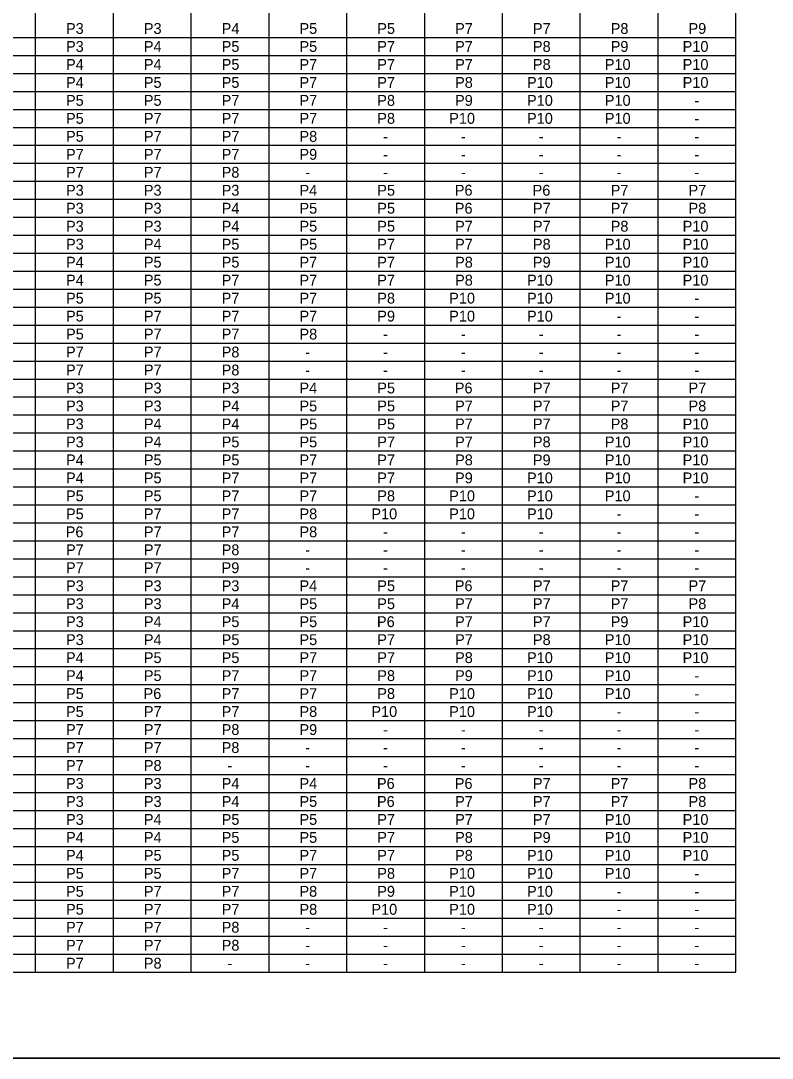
# Model space of a CAD drawing. Extents: x 637580 to 641008, y 294594 to 295782.
# Drawn here: x 640328.9 to 640536.7, y 295202.6 to 295489.6 of the extents above; entities that cross this region are included whole.
import ezdxf

# ---------------------------------------------------------------- set-up
doc = ezdxf.new("R2010")
doc.units = 0
doc.layers.add('1', color=7, linetype='Continuous')
doc.layers.add('2', color=7, linetype='Continuous')

msp = doc.modelspace()

# ---------------------------------------------------------------- linework, layer by layer
at = {"layer": '1'}
for p, q in [((640526.66, 295226.43), (640526.66, 295743.08)), ((640191.43, 295445.22), (640526.66, 295445.22)), ((640191.43, 295390.52), (640526.66, 295390.52)), ((640191.43, 295335.82), (640526.66, 295335.82)), ((640191.43, 295281.12), (640526.66, 295281.12)), ((640191.43, 295226.43), (640526.66, 295226.43)), ((640929.31, 295202.63), (640143.31, 295202.63)), ((640143.31, 295202.63), (640729.31, 295202.63))]:
    msp.add_line(p, q, dxfattribs=at)
at = {"layer": '2'}
for p, q in [((640333.02, 295226.43), (640333.02, 295728.06)), ((640354.53, 295226.43), (640354.53, 295728.06)), ((640376.05, 295226.43), (640376.05, 295728.06)), ((640397.56, 295226.43), (640397.56, 295728.06)), ((640419.08, 295226.43), (640419.08, 295728.06)), ((640440.6, 295226.43), (640440.6, 295728.06)), ((640462.11, 295226.43), (640462.11, 295728.06)), ((640483.63, 295226.43), (640483.63, 295728.06)), ((640505.14, 295226.43), (640505.14, 295728.06)), ((640218.95, 295485), (640526.66, 295485)), ((640218.95, 295480.02), (640526.66, 295480.02)), ((640218.95, 295475.05), (640526.66, 295475.05)), ((640218.95, 295470.08), (640526.66, 295470.08)), ((640218.95, 295465.11), (640526.66, 295465.11)), ((640218.95, 295460.13), (640526.66, 295460.13)), ((640218.95, 295455.16), (640526.66, 295455.16)), ((640218.95, 295450.19), (640526.66, 295450.19)), ((640218.95, 295440.24), (640526.66, 295440.24)), ((640218.95, 295435.27), (640526.66, 295435.27)), ((640218.95, 295430.3), (640526.66, 295430.3)), ((640218.95, 295425.33), (640526.66, 295425.33)), ((640218.95, 295420.35), (640526.66, 295420.35)), ((640218.95, 295415.38), (640526.66, 295415.38)), ((640218.95, 295410.41), (640526.66, 295410.41)), ((640218.95, 295405.44), (640526.66, 295405.44)), ((640218.95, 295400.46), (640526.66, 295400.46)), ((640218.95, 295395.49), (640526.66, 295395.49)), ((640218.95, 295385.55), (640526.66, 295385.55)), ((640218.95, 295380.57), (640526.66, 295380.57)), ((640218.95, 295375.6), (640526.66, 295375.6)), ((640218.95, 295370.63), (640526.66, 295370.63)), ((640218.95, 295365.66), (640526.66, 295365.66)), ((640218.95, 295360.68), (640526.66, 295360.68)), ((640218.95, 295355.71), (640526.66, 295355.71)), ((640218.95, 295350.74), (640526.66, 295350.74)), ((640218.95, 295345.77), (640526.66, 295345.77)), ((640218.95, 295340.79), (640526.66, 295340.79)), ((640218.95, 295330.85), (640526.66, 295330.85)), ((640218.95, 295325.88), (640526.66, 295325.88)), ((640218.95, 295320.9), (640526.66, 295320.9)), ((640218.95, 295315.93), (640526.66, 295315.93)), ((640218.95, 295310.96), (640526.66, 295310.96)), ((640218.95, 295305.99), (640526.66, 295305.99)), ((640218.95, 295301.01), (640526.66, 295301.01)), ((640218.95, 295296.04), (640526.66, 295296.04)), ((640218.95, 295291.07), (640526.66, 295291.07)), ((640218.95, 295286.1), (640526.66, 295286.1)), ((640218.95, 295276.15), (640526.66, 295276.15)), ((640218.95, 295271.18), (640526.66, 295271.18)), ((640218.95, 295266.21), (640526.66, 295266.21)), ((640218.95, 295261.23), (640526.66, 295261.23)), ((640218.95, 295256.26), (640526.66, 295256.26)), ((640218.95, 295251.29), (640526.66, 295251.29)), ((640218.95, 295246.32), (640526.66, 295246.32)), ((640218.95, 295241.34), (640526.66, 295241.34)), ((640218.95, 295236.37), (640526.66, 295236.37)), ((640218.95, 295231.4), (640526.66, 295231.4))]:
    msp.add_line(p, q, dxfattribs=at)

# ---------------------------------------------------------------- texts
at = {"layer": '1'}
for s, p in [('P3', (640341.42, 295485.98)), ('P3', (640362.94, 295485.98)), ('P4', (640384.46, 295485.98)), ('P5', (640405.97, 295485.98)), ('P5', (640427.49, 295485.98)), ('P7', (640449, 295485.98)), ('P7', (640470.52, 295485.98)), ('P8', (640492.03, 295485.98)), ('P9', (640513.54, 295485.98)), ('P3', (640341.42, 295481.01)), ('P4', (640362.94, 295481.01)), ('P5', (640384.46, 295481.01)), ('P5', (640405.97, 295481)), ('P7', (640427.49, 295481.01)), ('P7', (640449, 295481.01)), ('P8', (640470.52, 295481.01)), ('P9', (640492.02, 295481.01)), ('P10', (640511.92, 295481.01)), ('P4', (640341.42, 295476.04)), ('P4', (640362.94, 295476.04)), ('P5', (640384.46, 295476.04)), ('P7', (640405.97, 295476.03)), ('P7', (640427.49, 295476.04)), ('P7', (640449, 295476.04)), ('P8', (640470.52, 295476.04)), ('P10', (640490.4, 295476.04)), ('P10', (640511.92, 295476.04)), ('P4', (640341.42, 295471.06)), ('P5', (640362.94, 295471.06)), ('P5', (640384.46, 295471.06)), ('P7', (640405.97, 295471.06)), ('P7', (640427.49, 295471.06)), ('P8', (640449, 295471.06)), ('P10', (640468.89, 295471.06)), ('P10', (640490.4, 295471.06)), ('P10', (640511.92, 295471.06)), ('P5', (640341.42, 295466.09)), ('P5', (640362.94, 295466.09)), ('P7', (640384.46, 295466.09)), ('P7', (640405.97, 295466.09)), ('P8', (640427.49, 295466.09)), ('P9', (640448.99, 295466.09)), ('P10', (640468.89, 295466.09)), ('P10', (640490.4, 295466.09)), ('-', (640515.17, 295466.09)), ('P5', (640341.42, 295461.12)), ('P7', (640362.94, 295461.12)), ('P7', (640384.46, 295461.12)), ('P7', (640405.97, 295461.11)), ('P8', (640427.49, 295461.12)), ('P10', (640447.37, 295461.12)), ('P10', (640468.89, 295461.12)), ('P10', (640490.4, 295461.12)), ('-', (640515.17, 295461.12)), ('P5', (640341.42, 295456.15)), ('P7', (640362.94, 295456.15)), ('P7', (640384.46, 295456.15)), ('P8', (640405.97, 295456.14)), ('-', (640429.11, 295456.15)), ('-', (640450.62, 295456.15)), ('-', (640472.14, 295456.15)), ('-', (640493.65, 295456.15)), ('-', (640515.17, 295456.15)), ('P7', (640341.42, 295451.17)), ('P7', (640362.94, 295451.17)), ('P7', (640384.46, 295451.17)), ('P9', (640405.96, 295451.17)), ('-', (640429.11, 295451.17)), ('-', (640450.62, 295451.17)), ('-', (640472.14, 295451.17)), ('-', (640493.65, 295451.17)), ('-', (640515.17, 295451.17)), ('P7', (640341.42, 295446.2)), ('P7', (640362.94, 295446.2)), ('P8', (640384.46, 295446.2)), ('-', (640407.59, 295446.2)), ('-', (640429.11, 295446.2)), ('-', (640450.62, 295446.2)), ('-', (640472.14, 295446.2)), ('-', (640493.65, 295446.2)), ('-', (640515.17, 295446.2)), ('P3', (640341.42, 295441.23)), ('P3', (640362.94, 295441.23)), ('P3', (640384.46, 295441.23)), ('P4', (640405.97, 295441.22)), ('P5', (640427.49, 295441.23)), ('P6', (640448.92, 295441.23)), ('P6', (640470.44, 295441.23)), ('P7', (640492.03, 295441.23)), ('P7', (640513.55, 295441.23)), ('P3', (640341.42, 295436.26)), ('P3', (640362.94, 295436.26)), ('P4', (640384.46, 295436.26)), ('P5', (640405.97, 295436.25)), ('P5', (640427.49, 295436.26)), ('P6', (640448.92, 295436.26)), ('P7', (640470.52, 295436.26)), ('P7', (640492.03, 295436.26)), ('P8', (640513.55, 295436.26)), ('P3', (640341.42, 295431.28)), ('P3', (640362.94, 295431.28)), ('P4', (640384.46, 295431.28)), ('P5', (640405.97, 295431.28)), ('P5', (640427.49, 295431.28)), ('P7', (640449, 295431.28)), ('P7', (640470.52, 295431.28)), ('P8', (640492.03, 295431.28)), ('P10', (640511.92, 295431.28)), ('P3', (640341.42, 295426.31)), ('P4', (640362.94, 295426.31)), ('P5', (640384.46, 295426.31)), ('P5', (640405.97, 295426.31)), ('P7', (640427.49, 295426.31)), ('P7', (640449, 295426.31)), ('P8', (640470.52, 295426.31)), ('P10', (640490.4, 295426.31)), ('P10', (640511.92, 295426.31)), ('P4', (640341.42, 295421.34)), ('P5', (640362.94, 295421.34)), ('P5', (640384.46, 295421.34)), ('P7', (640405.97, 295421.33)), ('P7', (640427.49, 295421.34)), ('P8', (640449, 295421.34)), ('P9', (640470.51, 295421.34)), ('P10', (640490.4, 295421.34)), ('P10', (640511.92, 295421.34)), ('P4', (640341.42, 295416.37)), ('P5', (640362.94, 295416.37)), ('P7', (640384.46, 295416.37)), ('P7', (640405.97, 295416.36)), ('P7', (640427.49, 295416.37)), ('P8', (640449, 295416.37)), ('P10', (640468.89, 295416.37)), ('P10', (640490.4, 295416.37)), ('P10', (640511.92, 295416.37)), ('P5', (640341.42, 295411.39)), ('P5', (640362.94, 295411.39)), ('P7', (640384.46, 295411.39)), ('P7', (640405.97, 295411.39)), ('P8', (640427.49, 295411.39)), ('P10', (640447.37, 295411.39)), ('P10', (640468.89, 295411.39)), ('P10', (640490.4, 295411.39)), ('-', (640515.17, 295411.39)), ('P5', (640341.42, 295406.42)), ('P7', (640362.94, 295406.42)), ('P7', (640384.46, 295406.42)), ('P7', (640405.97, 295406.42)), ('P9', (640427.48, 295406.42)), ('P10', (640447.37, 295406.42)), ('P10', (640468.89, 295406.42)), ('-', (640493.65, 295406.42)), ('-', (640515.17, 295406.42)), ('P5', (640341.42, 295401.45)), ('P7', (640362.94, 295401.45)), ('P7', (640384.46, 295401.45)), ('P8', (640405.97, 295401.44)), ('-', (640429.11, 295401.45)), ('-', (640450.62, 295401.45)), ('-', (640472.14, 295401.45)), ('-', (640493.65, 295401.45)), ('-', (640515.17, 295401.45)), ('P7', (640341.42, 295396.48)), ('P7', (640362.94, 295396.48)), ('P8', (640384.46, 295396.48)), ('-', (640407.59, 295396.47)), ('-', (640429.11, 295396.48)), ('-', (640450.62, 295396.48)), ('-', (640472.14, 295396.48)), ('-', (640493.65, 295396.48)), ('-', (640515.17, 295396.48)), ('P7', (640341.42, 295391.5)), ('P7', (640362.94, 295391.5)), ('P8', (640384.46, 295391.5)), ('-', (640407.59, 295391.5)), ('-', (640429.11, 295391.5)), ('-', (640450.62, 295391.5)), ('-', (640472.14, 295391.5)), ('-', (640493.65, 295391.5)), ('-', (640515.17, 295391.5)), ('P3', (640341.42, 295386.53)), ('P3', (640362.94, 295386.53)), ('P3', (640384.46, 295386.53)), ('P4', (640405.97, 295386.53)), ('P5', (640427.49, 295386.53)), ('P6', (640448.92, 295386.53)), ('P7', (640470.52, 295386.53)), ('P7', (640492.03, 295386.53)), ('P7', (640513.55, 295386.53)), ('P3', (640341.42, 295381.56)), ('P3', (640362.94, 295381.56)), ('P4', (640384.46, 295381.56)), ('P5', (640405.97, 295381.55)), ('P5', (640427.49, 295381.56)), ('P7', (640449, 295381.56)), ('P7', (640470.52, 295381.56)), ('P7', (640492.03, 295381.56)), ('P8', (640513.55, 295381.56)), ('P3', (640341.42, 295376.59)), ('P4', (640362.94, 295376.59)), ('P4', (640384.46, 295376.59)), ('P5', (640405.97, 295376.58)), ('P5', (640427.49, 295376.59)), ('P7', (640449, 295376.59)), ('P7', (640470.52, 295376.59)), ('P8', (640492.03, 295376.59)), ('P10', (640511.92, 295376.59)), ('P3', (640341.42, 295371.61)), ('P4', (640362.94, 295371.61)), ('P5', (640384.46, 295371.61)), ('P5', (640405.97, 295371.61)), ('P7', (640427.49, 295371.61)), ('P7', (640449, 295371.61)), ('P8', (640470.52, 295371.61)), ('P10', (640490.4, 295371.61)), ('P10', (640511.92, 295371.61)), ('P4', (640341.42, 295366.64)), ('P5', (640362.94, 295366.64)), ('P5', (640384.46, 295366.64)), ('P7', (640405.97, 295366.64)), ('P7', (640427.49, 295366.64)), ('P8', (640449, 295366.64)), ('P9', (640470.51, 295366.64)), ('P10', (640490.4, 295366.64)), ('P10', (640511.92, 295366.64)), ('P4', (640341.42, 295361.67)), ('P5', (640362.94, 295361.67)), ('P7', (640384.46, 295361.67)), ('P7', (640405.97, 295361.66)), ('P7', (640427.49, 295361.67)), ('P9', (640448.99, 295361.67)), ('P10', (640468.89, 295361.67)), ('P10', (640490.4, 295361.67)), ('P10', (640511.92, 295361.67)), ('P5', (640341.42, 295356.7)), ('P5', (640362.94, 295356.7)), ('P7', (640384.46, 295356.7)), ('P7', (640405.97, 295356.69)), ('P8', (640427.49, 295356.7)), ('P10', (640447.37, 295356.7)), ('P10', (640468.89, 295356.7)), ('P10', (640490.4, 295356.7)), ('-', (640515.17, 295356.7)), ('P5', (640341.42, 295351.72)), ('P7', (640362.94, 295351.72)), ('P7', (640384.46, 295351.72)), ('P8', (640405.97, 295351.72)), ('P10', (640425.86, 295351.72)), ('P10', (640447.37, 295351.72)), ('P10', (640468.89, 295351.72)), ('-', (640493.65, 295351.72)), ('-', (640515.17, 295351.72)), ('P6', (640341.34, 295346.75)), ('P7', (640362.94, 295346.75)), ('P7', (640384.46, 295346.75)), ('P8', (640405.97, 295346.75)), ('-', (640429.11, 295346.75)), ('-', (640450.62, 295346.75)), ('-', (640472.14, 295346.75)), ('-', (640493.65, 295346.75)), ('-', (640515.17, 295346.75)), ('P7', (640341.42, 295341.78)), ('P7', (640362.94, 295341.78)), ('P8', (640384.46, 295341.78)), ('-', (640407.59, 295341.77)), ('-', (640429.11, 295341.78)), ('-', (640450.62, 295341.78)), ('-', (640472.14, 295341.78)), ('-', (640493.65, 295341.78)), ('-', (640515.17, 295341.78)), ('P7', (640341.42, 295336.81)), ('P7', (640362.94, 295336.81)), ('P9', (640384.44, 295336.81)), ('-', (640407.59, 295336.8)), ('-', (640429.11, 295336.81)), ('-', (640450.62, 295336.81)), ('-', (640472.14, 295336.81)), ('-', (640493.65, 295336.81)), ('-', (640515.17, 295336.81)), ('P3', (640341.42, 295331.83)), ('P3', (640362.94, 295331.83)), ('P3', (640384.46, 295331.83)), ('P4', (640405.97, 295331.83)), ('P5', (640427.49, 295331.83)), ('P6', (640448.92, 295331.83)), ('P7', (640470.52, 295331.83)), ('P7', (640492.03, 295331.83)), ('P7', (640513.55, 295331.83)), ('P3', (640341.42, 295326.86)), ('P3', (640362.94, 295326.86)), ('P4', (640384.46, 295326.86)), ('P5', (640405.97, 295326.86)), ('P5', (640427.49, 295326.86)), ('P7', (640449, 295326.86)), ('P7', (640470.52, 295326.86)), ('P7', (640492.03, 295326.86)), ('P8', (640513.55, 295326.86)), ('P3', (640341.42, 295321.89)), ('P4', (640362.94, 295321.89)), ('P5', (640384.46, 295321.89)), ('P5', (640405.97, 295321.88)), ('P6', (640427.4, 295321.89)), ('P7', (640449, 295321.89)), ('P7', (640470.52, 295321.89)), ('P9', (640492.02, 295321.89)), ('P10', (640511.92, 295321.89)), ('P3', (640341.42, 295316.92)), ('P4', (640362.94, 295316.92)), ('P5', (640384.46, 295316.92)), ('P5', (640405.97, 295316.91)), ('P7', (640427.49, 295316.92)), ('P7', (640449, 295316.92)), ('P8', (640470.52, 295316.92)), ('P10', (640490.4, 295316.92)), ('P10', (640511.92, 295316.92)), ('P4', (640341.42, 295311.94)), ('P5', (640362.94, 295311.94)), ('P5', (640384.46, 295311.94)), ('P7', (640405.97, 295311.94)), ('P7', (640427.49, 295311.94)), ('P8', (640449, 295311.94)), ('P10', (640468.89, 295311.94)), ('P10', (640490.4, 295311.94)), ('P10', (640511.92, 295311.94)), ('P4', (640341.42, 295306.97)), ('P5', (640362.94, 295306.97)), ('P7', (640384.46, 295306.97)), ('P7', (640405.97, 295306.97)), ('P8', (640427.49, 295306.97)), ('P9', (640448.99, 295306.97)), ('P10', (640468.89, 295306.97)), ('P10', (640490.4, 295306.97)), ('-', (640515.17, 295306.97)), ('P5', (640341.42, 295302)), ('P6', (640362.86, 295302)), ('P7', (640384.46, 295302)), ('P7', (640405.97, 295301.99)), ('P8', (640427.49, 295302)), ('P10', (640447.37, 295302)), ('P10', (640468.89, 295302)), ('P10', (640490.4, 295302)), ('-', (640515.17, 295302)), ('P5', (640341.42, 295297.03)), ('P7', (640362.94, 295297.03)), ('P7', (640384.46, 295297.03)), ('P8', (640405.97, 295297.02)), ('P10', (640425.86, 295297.03)), ('P10', (640447.37, 295297.03)), ('P10', (640468.89, 295297.03)), ('-', (640493.65, 295297.03)), ('-', (640515.17, 295297.03)), ('P7', (640341.42, 295292.05)), ('P7', (640362.94, 295292.05)), ('P8', (640384.46, 295292.05)), ('P9', (640405.96, 295292.05)), ('-', (640429.11, 295292.05)), ('-', (640450.62, 295292.05)), ('-', (640472.14, 295292.05)), ('-', (640493.65, 295292.05)), ('-', (640515.17, 295292.05)), ('P7', (640341.42, 295287.08)), ('P7', (640362.94, 295287.08)), ('P8', (640384.46, 295287.08)), ('-', (640407.59, 295287.08)), ('-', (640429.11, 295287.08)), ('-', (640450.62, 295287.08)), ('-', (640472.14, 295287.08)), ('-', (640493.65, 295287.08)), ('-', (640515.17, 295287.08)), ('P7', (640341.42, 295282.11)), ('P8', (640362.94, 295282.11)), ('-', (640386.07, 295282.11)), ('-', (640407.59, 295282.1)), ('-', (640429.11, 295282.11)), ('-', (640450.62, 295282.11)), ('-', (640472.14, 295282.11)), ('-', (640493.65, 295282.11)), ('-', (640515.17, 295282.11)), ('P3', (640341.42, 295277.14)), ('P3', (640362.94, 295277.14)), ('P4', (640384.46, 295277.14)), ('P4', (640405.97, 295277.13)), ('P6', (640427.4, 295277.14)), ('P6', (640448.92, 295277.14)), ('P7', (640470.52, 295277.14)), ('P7', (640492.03, 295277.14)), ('P8', (640513.55, 295277.14)), ('P3', (640341.42, 295272.16)), ('P3', (640362.94, 295272.16)), ('P4', (640384.46, 295272.16)), ('P5', (640405.97, 295272.16)), ('P6', (640427.4, 295272.16)), ('P7', (640449, 295272.16)), ('P7', (640470.52, 295272.16)), ('P7', (640492.03, 295272.16)), ('P8', (640513.55, 295272.16)), ('P3', (640341.42, 295267.19)), ('P4', (640362.94, 295267.19)), ('P5', (640384.46, 295267.19)), ('P5', (640405.97, 295267.19)), ('P7', (640427.49, 295267.19)), ('P7', (640449, 295267.19)), ('P7', (640470.52, 295267.19)), ('P10', (640490.4, 295267.19)), ('P10', (640511.92, 295267.19)), ('P4', (640341.42, 295262.22)), ('P4', (640362.94, 295262.22)), ('P5', (640384.46, 295262.22)), ('P5', (640405.97, 295262.21)), ('P7', (640427.49, 295262.22)), ('P8', (640449, 295262.22)), ('P9', (640470.51, 295262.22)), ('P10', (640490.4, 295262.22)), ('P10', (640511.92, 295262.22)), ('P4', (640341.42, 295257.25)), ('P5', (640362.94, 295257.25)), ('P5', (640384.46, 295257.25)), ('P7', (640405.97, 295257.24)), ('P7', (640427.49, 295257.25)), ('P8', (640449, 295257.25)), ('P10', (640468.89, 295257.25)), ('P10', (640490.4, 295257.25)), ('P10', (640511.92, 295257.25)), ('P5', (640341.42, 295252.27)), ('P5', (640362.94, 295252.27)), ('P7', (640384.46, 295252.27)), ('P7', (640405.97, 295252.27)), ('P8', (640427.49, 295252.27)), ('P10', (640447.37, 295252.27)), ('P10', (640468.89, 295252.27)), ('P10', (640490.4, 295252.27)), ('-', (640515.17, 295252.27)), ('P5', (640341.42, 295247.3)), ('P7', (640362.94, 295247.3)), ('P7', (640384.46, 295247.3)), ('P8', (640405.97, 295247.3)), ('P9', (640427.48, 295247.3)), ('P10', (640447.37, 295247.3)), ('P10', (640468.89, 295247.3)), ('-', (640493.65, 295247.3)), ('-', (640515.17, 295247.3)), ('P5', (640341.42, 295242.33)), ('P7', (640362.94, 295242.33)), ('P7', (640384.46, 295242.33)), ('P8', (640405.97, 295242.32)), ('P10', (640425.86, 295242.33)), ('P10', (640447.37, 295242.33)), ('P10', (640468.89, 295242.33)), ('-', (640493.65, 295242.33)), ('-', (640515.17, 295242.33)), ('P7', (640341.42, 295237.36)), ('P7', (640362.94, 295237.36)), ('P8', (640384.46, 295237.36)), ('-', (640407.59, 295237.35)), ('-', (640429.11, 295237.36)), ('-', (640450.62, 295237.36)), ('-', (640472.14, 295237.36)), ('-', (640493.65, 295237.36)), ('-', (640515.17, 295237.36)), ('P7', (640341.42, 295232.38)), ('P7', (640362.94, 295232.38)), ('P8', (640384.46, 295232.38)), ('-', (640407.59, 295232.38)), ('-', (640429.11, 295232.38)), ('-', (640450.62, 295232.38)), ('-', (640472.14, 295232.38)), ('-', (640493.65, 295232.38)), ('-', (640515.17, 295232.38)), ('P7', (640341.42, 295227.41)), ('P8', (640362.94, 295227.41)), ('-', (640386.07, 295227.41)), ('-', (640407.59, 295227.41)), ('-', (640429.11, 295227.41)), ('-', (640450.62, 295227.41)), ('-', (640472.14, 295227.41)), ('-', (640493.65, 295227.41)), ('-', (640515.17, 295227.41))]:
    msp.add_text(s, height=3, dxfattribs=at).set_placement(p)

doc.saveas('drawing.dxf')
